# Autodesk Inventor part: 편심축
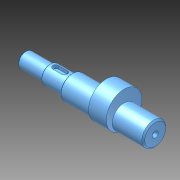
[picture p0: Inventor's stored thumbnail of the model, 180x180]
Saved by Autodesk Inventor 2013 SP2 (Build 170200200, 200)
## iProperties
Created: 2025-04
Part Number: 편심축
Material: Generic
Document SubType Name: Modeling
Designer: 601
Density: 1 g/cm^3
Author: 601
변환 표준: STEP AP214IS
전처리기: Build: 200, Release: 2013 SP2 Update 6 - Date: Thu 07/17/2014
전송 단위: 밀리미터
불확실성: 0.01
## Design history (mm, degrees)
node "편심축1"
node "솔리드1"
node "기준1"
